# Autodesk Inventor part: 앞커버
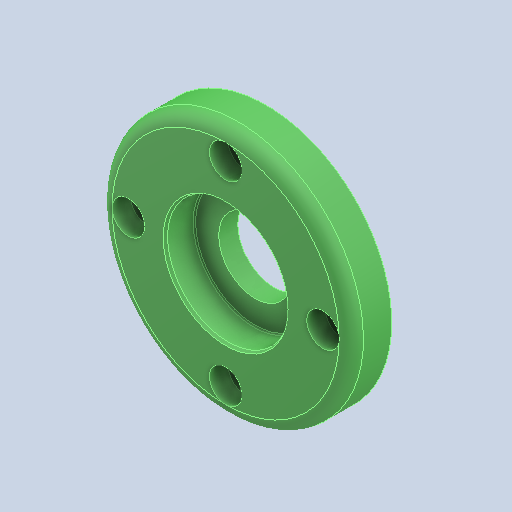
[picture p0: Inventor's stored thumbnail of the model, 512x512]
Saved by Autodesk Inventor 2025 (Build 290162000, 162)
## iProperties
Created: 2024-07
Part Number: 앞커버
Material: 알루미늄 6061
Document SubType Name: Modeling
Designer: anfro
Density: 2.71 g/cm^3
Appearance: 기본값
Author: jhkim
Sending System: Autodesk Inventor 2025
Preprocessor: ST-DEVELOPER v20
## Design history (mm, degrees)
feature "솔리드1"
node "솔리드2"
